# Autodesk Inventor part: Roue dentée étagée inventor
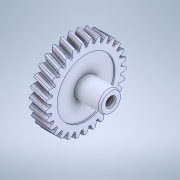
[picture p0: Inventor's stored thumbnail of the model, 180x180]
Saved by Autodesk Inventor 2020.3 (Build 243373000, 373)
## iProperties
Created: 2019-01
Part Number: Roue dentée étagée inventor
Material: Générique
Document SubType Name: Modeling
Designer: ficho
Density: 1 g/cm^3
Appearance: Par défaut
Sending System: SolidWorks 2015
Last Author: adrien
Last Saved: 2019-01-11
Author: ficho
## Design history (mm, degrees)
feature "Répétition circulaire2"
sketch "Esquisse1"
  geometry: A1 r 2.909 centre (2.327, 2.55) between (-0.532, 3.086) and (-0.58, 2.432) reference; A2 r 2.5 centre (0, 0) between (0.58, 2.432) and (-0.58, 2.432) reference; A3 r 2.909 centre (-2.327, 2.55) between (0.58, 2.432) and (0.532, 3.086) reference; A4 r 4.512 centre (-3.648, 1.389) between (0.532, 3.086) and (0.2, 3.745) reference; A5 r 3.75 centre (0, 0) between (0.2, 3.745) and (-0.2, 3.745) reference; A6 r 4.512 centre (3.648, 1.389) between (-0.2, 3.745) and (-0.532, 3.086) reference; A7 r 2.909 centre (0.384, 3.431) between (-2.245, 2.184) and (-1.899, 1.627) reference; A8 r 2.5 centre (0, 0) between (-0.96, 2.308) and (-1.899, 1.627) reference; A9 r 2.909 centre (-3.381, 0.695) between (-0.96, 2.308) and (-1.383, 2.81) reference; A10 r 4.512 centre (-3.768, -1.02) between (-1.383, 2.81) and (-2.039, 3.147) reference; A11 r 3.75 centre (0, 0) between (-2.039, 3.147) and (-2.363, 2.912) reference; A12 r 4.512 centre (2.135, 3.268) between (-2.363, 2.912) and (-2.245, 2.184) reference; A13 r 2.909 centre (-1.706, 3.001) between (-3.1, 0.447) and (-2.492, 0.2) reference; A14 r 2.5 centre (0, 0) between (-2.134, 1.303) and (-2.492, 0.2) reference; A15 r 2.909 centre (-3.144, -1.425) between (-2.134, 1.303) and (-2.771, 1.46) reference; A16 r 4.512 centre (-2.448, -3.04) between (-2.771, 1.46) and (-3.5, 1.347) reference; A17 r 3.75 centre (0, 0) between (-3.5, 1.347) and (-3.623, 0.967) reference; A18 r 4.512 centre (-0.194, 3.899) between (-3.623, 0.967) and (-3.1, 0.447) reference; A19 r 2.909 centre (-3.144, 1.425) between (-2.771, -1.46) and (-2.134, -1.303) reference; A20 r 2.5 centre (0, 0) between (-2.492, -0.2) and (-2.134, -1.303) reference; A21 r 2.909 centre (-1.706, -3.001) between (-2.492, -0.2) and (-3.1, -0.447) reference; A22 r 4.512 centre (-0.194, -3.899) between (-3.1, -0.447) and (-3.623, -0.967) reference; A23 r 3.75 centre (0, 0) between (-3.623, -0.967) and (-3.5, -1.347) reference; A24 r 4.512 centre (-2.448, 3.04) between (-3.5, -1.347) and (-2.771, -1.46) reference; A25 r 2.909 centre (-3.381, -0.695) between (-1.383, -2.81) and (-0.96, -2.308) reference; A26 r 2.5 centre (0, 0) between (-1.899, -1.627) and (-0.96, -2.308) reference; A27 r 2.909 centre (0.384, -3.431) between (-1.899, -1.627) and (-2.245, -2.184) reference; A28 r 4.512 centre (2.135, -3.268) between (-2.245, -2.184) and (-2.363, -2.912) reference; A29 r 3.75 centre (0, 0) between (-2.363, -2.912) and (-2.039, -3.147) reference; A30 r 4.512 centre (-3.768, 1.02) between (-2.039, -3.147) and (-1.383, -2.81) reference; A31 r 2.909 centre (-2.327, -2.55) between (0.532, -3.086) and (0.58, -2.432) reference; A32 r 2.5 centre (0, 0) between (-0.58, -2.432) and (0.58, -2.432) reference; A33 r 2.909 centre (2.327, -2.55) between (-0.58, -2.432) and (-0.532, -3.086) reference; A34 r 4.512 centre (3.648, -1.389) between (-0.532, -3.086) and (-0.2, -3.745) reference; A35 r 3.75 centre (0, 0) between (-0.2, -3.745) and (0.2, -3.745) reference; A36 r 4.512 centre (-3.648, -1.389) between (0.2, -3.745) and (0.532, -3.086) reference; A37 r 2.909 centre (-0.384, -3.431) between (2.245, -2.184) and (1.899, -1.627) reference; A38 r 2.5 centre (0, 0) between (0.96, -2.308) and (1.899, -1.627) reference; A39 r 2.909 centre (3.381, -0.695) between (0.96, -2.308) and (1.383, -2.81) reference; A40 r 4.512 centre (3.768, 1.02) between (1.383, -2.81) and (2.039, -3.147) reference; A41 r 3.75 centre (0, 0) between (2.039, -3.147) and (2.363, -2.912) reference; A42 r 4.512 centre (-2.135, -3.268) between (2.363, -2.912) and (2.245, -2.184) reference; A43 r 2.909 centre (1.706, -3.001) between (3.1, -0.447) and (2.492, -0.2) reference; A44 r 2.5 centre (0, 0) between (2.134, -1.303) and (2.492, -0.2) reference; A45 r 2.909 centre (3.144, 1.425) between (2.134, -1.303) and (2.771, -1.46) reference; A46 r 4.512 centre (2.448, 3.04) between (2.771, -1.46) and (3.5, -1.347) reference; A47 r 3.75 centre (0, 0) between (3.5, -1.347) and (3.623, -0.967) reference; A48 r 4.512 centre (0.194, -3.899) between (3.623, -0.967) and (3.1, -0.447) reference; A49 r 2.909 centre (3.144, -1.425) between (2.771, 1.46) and (2.134, 1.303) reference; A50 r 2.5 centre (0, 0) between (2.492, 0.2) and (2.134, 1.303) reference; A51 r 2.909 centre (1.706, 3.001) between (2.492, 0.2) and (3.1, 0.447) reference; A52 r 4.512 centre (0.194, 3.899) between (3.1, 0.447) and (3.623, 0.967) reference; A53 r 3.75 centre (0, 0) between (3.623, 0.967) and (3.5, 1.347) reference; A54 r 4.512 centre (2.448, -3.04) between (3.5, 1.347) and (2.771, 1.46) reference; A55 r 2.909 centre (3.381, 0.695) between (1.383, 2.81) and (0.96, 2.308) reference; A56 r 2.5 centre (0, 0) between (1.899, 1.627) and (0.96, 2.308) reference; A57 r 2.909 centre (-0.384, 3.431) between (1.899, 1.627) and (2.245, 2.184) reference; A58 r 4.512 centre (-2.135, 3.268) between (2.245, 2.184) and (2.363, 2.912) reference; A59 r 3.75 centre (0, 0) between (2.363, 2.912) and (2.039, 3.147) reference; A60 r 4.512 centre (3.768, -1.02) between (2.039, 3.147) and (1.383, 2.81) reference; 2 further points
extrude "Extrusion1" cut sketch "Esquisse1" extent not by distance; stored distance "d0" = 6.2; taper "d1" = 0 deg
node "Solide1"
node "Boucle projetée1"
node "Boucle projetée2"
node "Boucle projetée3"
node "Boucle projetée4"
node "Boucle projetée5"
node "Boucle projetée6"
node "Boucle projetée7"
node "Boucle projetée8"
node "Boucle projetée9"
node "Boucle projetée10"
